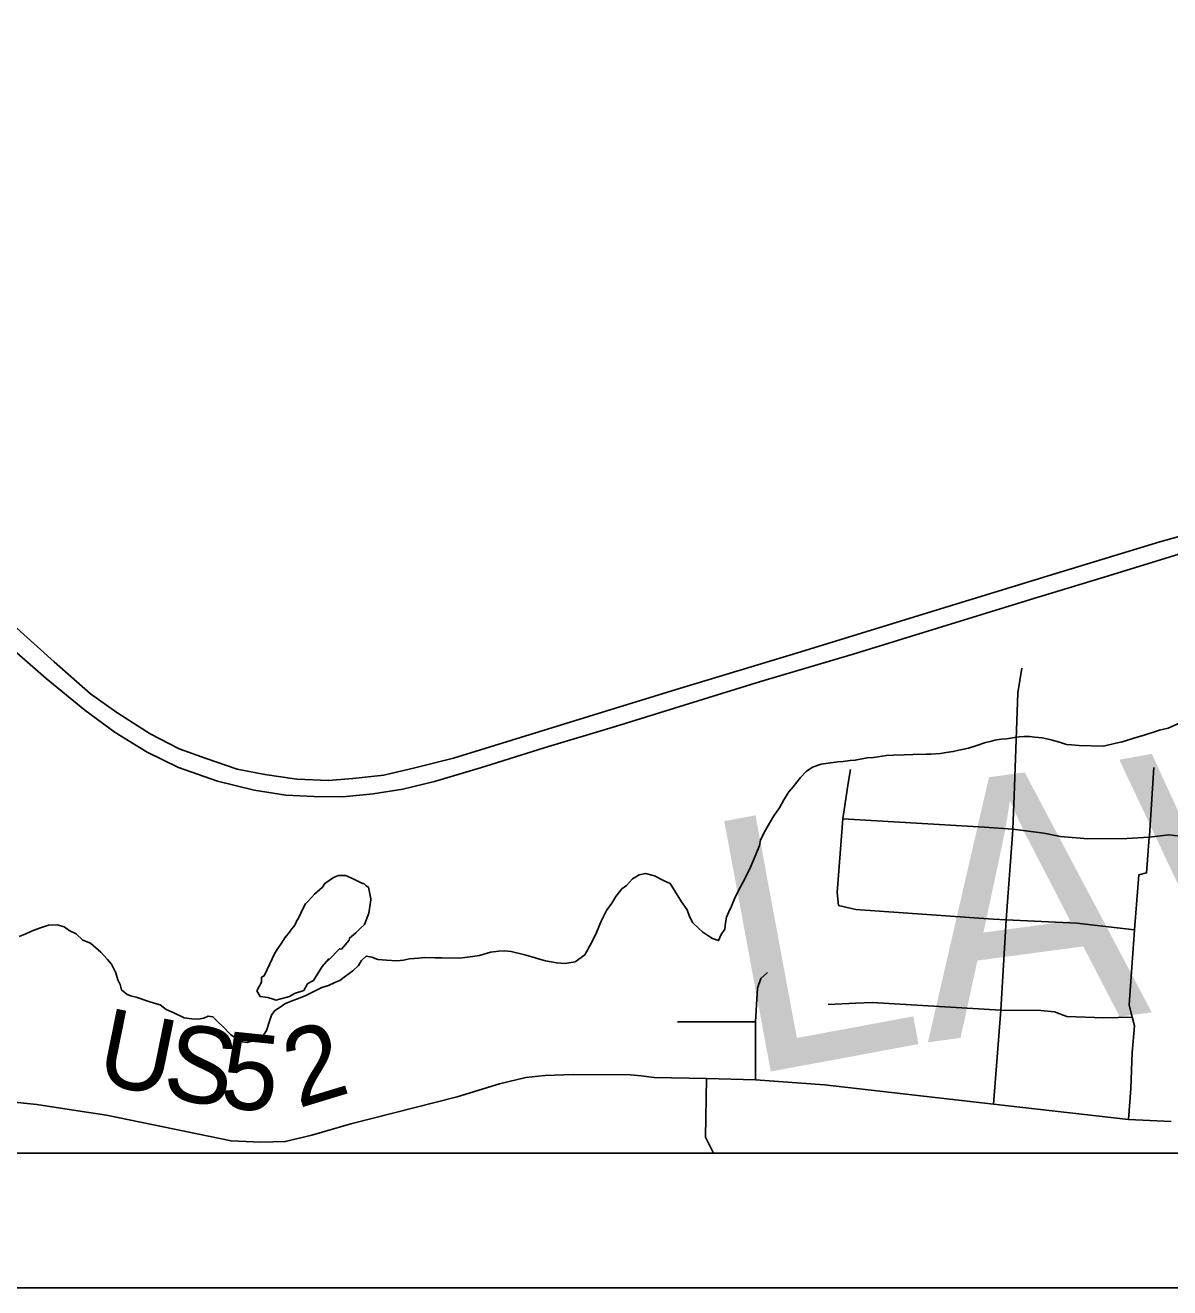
# Model space of a CAD drawing. Extents: x 0 to 45.4, y -2.2 to 22.
# Drawn here: x 5.991 to 6.842, y 14 to 14.939 of the extents above; entities that cross this region are included whole.
import ezdxf

# ---------------------------------------------------------------- set-up
doc = ezdxf.new("R2010")
doc.units = 0
for name, color, linetype in [('GM_X_Corporation', 7, 'Continuous'), ('GM_X_County_Road', 7, 'Continuous'), ('GM_X_County_Road_Text', 7, 'Continuous'), ('GM_X_County_Text', 7, 'Continuous'), ('GM_X_Minor_Lake', 7, 'Continuous'), ('GM_X_Minor_River', 7, 'Continuous'), ('GM_X_Township_Road', 7, 'Continuous'), ('GM_X_US_Route', 7, 'Continuous'), ('SH_Data', 7, 'Continuous')]:
    doc.layers.add(name, color=color, linetype=linetype)

msp = doc.modelspace()

# ---------------------------------------------------------------- linework, layer by layer
at = {"layer": 'GM_X_Corporation'}
for points in [[(5.60214, 14.1), (7.04133, 14.1), (7.11457, 14.11359), (7.56084, 14.21938), (7.62443, 14.24441), (8.08317, 14.39725), (8.47114, 14.54063), (8.59074, 14.58235), (8.82276, 14.67719), (8.9, 14.71924), (8.9, 20.9), (2.1, 20.9)], [(5.60214, 14.1), (7.04133, 14.1), (7.11457, 14.11359), (7.56084, 14.21938), (7.62443, 14.24441), (8.08317, 14.39725), (8.47114, 14.54063), (8.59074, 14.58235), (8.82276, 14.67719), (8.9, 14.71924), (8.9, 20.9), (6.29416, 20.9), (6.28823, 20.82258), (6.27886, 20.7002), (6.25885, 20.2929), (6.25376, 20.20761), (6.23458, 20.00881), (6.2236, 19.85421), (6.18097, 19.25389), (6.17632, 19.18849), (6.10611, 18.16069), (5.64203, 18.19082)]]:
    msp.add_lwpolyline(points, dxfattribs=at)
at = {"layer": 'GM_X_County_Road'}
msp.add_lwpolyline([(5.96573, 14.13987), (5.9995, 14.13616), (6.02998, 14.13163), (6.0514, 14.12833), (6.14408, 14.10938), (6.16578, 14.10835), (6.18421, 14.10871), (6.20409, 14.1134), (6.23287, 14.12181), (6.31216, 14.14198), (6.34364, 14.15174), (6.36299, 14.15624), (6.37715, 14.15781), (6.39853, 14.15871), (6.44082, 14.15826), (6.44892, 14.15758), (6.45859, 14.15646), (6.49741, 14.15552), (6.53392, 14.15475), (6.58504, 14.1509), (6.71072, 14.13661), (6.81118, 14.12521), (6.84298, 14.12365)], dxfattribs=at)
at = {"layer": 'GM_X_Minor_Lake'}
for points in [[(6.23473, 14.30404), (6.22906, 14.3067), (6.22377, 14.30671), (6.21999, 14.30519), (6.21356, 14.30065), (6.21204, 14.298), (6.20599, 14.2927), (6.20145, 14.28778), (6.19918, 14.28551), (6.19728, 14.28172), (6.19425, 14.27527), (6.19236, 14.27224), (6.19236, 14.27186), (6.19123, 14.26959), (6.1882, 14.2658), (6.1882, 14.26542), (6.18404, 14.2605), (6.18441, 14.26088), (6.18101, 14.25557), (6.17911, 14.25292), (6.17646, 14.24875), (6.17078, 14.23662), (6.16851, 14.23208), (6.16662, 14.23094), (6.16662, 14.22715), (6.16321, 14.22071)], [(6.16321, 14.22071), (6.16548, 14.21653), (6.17115, 14.21577), (6.17531, 14.21463), (6.1772, 14.21387), (6.18741, 14.21651), (6.19119, 14.21878), (6.198, 14.22104), (6.20065, 14.22597), (6.2033, 14.22748), (6.20519, 14.22861), (6.21163, 14.23884), (6.21655, 14.24453), (6.21655, 14.24377), (6.22449, 14.2521), (6.226, 14.25172), (6.23168, 14.25854), (6.23206, 14.26005), (6.2366, 14.26384), (6.23963, 14.26687), (6.24303, 14.27027), (6.24644, 14.27861), (6.24796, 14.28847), (6.24796, 14.28923), (6.24608, 14.29795), (6.24456, 14.29871), (6.24267, 14.30061), (6.24154, 14.30062), (6.23473, 14.30404)]]:
    msp.add_lwpolyline(points, dxfattribs=at)
at = {"layer": 'GM_X_Minor_River'}
for points in [[(6.79268, 14.40287), (6.80181, 14.40499), (6.80675, 14.40605), (6.81589, 14.40893), (6.82198, 14.41072), (6.83417, 14.41469), (6.84064, 14.4161), (6.85019, 14.42049)], [(6.3005, 14.24533), (6.31376, 14.2451), (6.32173, 14.2461), (6.32857, 14.24713), (6.33695, 14.24964), (6.34302, 14.2503), (6.34719, 14.25061), (6.35211, 14.25014), (6.36229, 14.24769), (6.36756, 14.24608), (6.37322, 14.24447), (6.37774, 14.24325), (6.38605, 14.24159), (6.3921, 14.24111), (6.3997, 14.2425), (6.40699, 14.24769), (6.41208, 14.2571), (6.41561, 14.26425), (6.41917, 14.27255), (6.4231, 14.28045), (6.42698, 14.28608), (6.4301, 14.29096), (6.43437, 14.29659), (6.43782, 14.29919), (6.44245, 14.30404), (6.44743, 14.307), (6.45199, 14.30806), (6.45878, 14.30642), (6.46591, 14.30251), (6.47042, 14.30053), (6.47374, 14.29554), (6.4789, 14.2871), (6.48296, 14.28095), (6.48476, 14.27598), (6.48733, 14.27138), (6.49143, 14.26752), (6.49479, 14.26442), (6.49853, 14.26208), (6.5019, 14.25974), (6.50642, 14.25815), (6.50839, 14.26267), (6.51112, 14.2668), (6.51158, 14.27135), (6.51241, 14.27551), (6.51399, 14.27966), (6.51596, 14.2838), (6.51873, 14.29059), (6.52265, 14.29812), (6.52617, 14.30452), (6.53011, 14.3128), (6.53406, 14.32223), (6.53683, 14.32902), (6.53766, 14.3328), (6.54041, 14.33845), (6.54432, 14.3456), (6.54745, 14.35086), (6.55172, 14.35686), (6.55485, 14.36288), (6.55875, 14.36889), (6.56184, 14.37264), (6.56727, 14.37938), (6.57151, 14.38386), (6.57612, 14.3872), (6.58259, 14.38937), (6.58791, 14.39004), (6.59512, 14.39105), (6.59892, 14.39137), (6.60423, 14.39204), (6.60802, 14.39235), (6.61677, 14.3941), (6.6217, 14.3944), (6.63119, 14.39576), (6.6365, 14.39605), (6.64446, 14.39629), (6.6509, 14.39656), (6.66075, 14.39677), (6.66416, 14.39671), (6.67137, 14.39735), (6.67555, 14.39804), (6.68087, 14.3987), (6.68505, 14.39977), (6.68885, 14.40047), (6.69227, 14.40117), (6.69761, 14.40298), (6.70485, 14.40551), (6.70827, 14.40621), (6.7117, 14.40729), (6.71663, 14.40797), (6.72043, 14.40828), (6.72498, 14.40896), (6.72992, 14.40964), (6.73371, 14.40995), (6.7375, 14.40989), (6.74166, 14.40944), (6.74695, 14.40897), (6.75262, 14.40773), (6.75978, 14.40571), (6.76505, 14.4041), (6.76883, 14.40366), (6.7745, 14.40318), (6.79268, 14.40287)], [(5.98637, 14.26128), (5.99133, 14.26309), (5.99553, 14.2653), (6.00163, 14.26748), (6.00811, 14.26965), (6.01456, 14.26992), (6.01983, 14.26831), (6.02357, 14.26559), (6.02883, 14.26322), (6.03367, 14.25858), (6.03931, 14.25621), (6.04715, 14.24962), (6.05198, 14.24422), (6.05495, 14.24076), (6.05825, 14.23424), (6.05967, 14.2289), (6.0615, 14.22545), (6.06257, 14.22164), (6.06668, 14.21815), (6.07007, 14.21696), (6.07346, 14.21614), (6.08288, 14.21294), (6.08664, 14.21174), (6.09117, 14.21052), (6.09565, 14.20703), (6.10091, 14.20466), (6.10918, 14.20073), (6.11484, 14.19987), (6.11939, 14.1998), (6.12357, 14.20048), (6.127, 14.20194), (6.1304, 14.20151), (6.13413, 14.19765), (6.13785, 14.19417), (6.14343, 14.18837), (6.14755, 14.18565), (6.15243, 14.18291), (6.15583, 14.18247), (6.1623, 14.18426), (6.16609, 14.18457), (6.17038, 14.19134), (6.17239, 14.19814), (6.17399, 14.20267), (6.17632, 14.20604), (6.18053, 14.20863), (6.18399, 14.21123), (6.18857, 14.21305), (6.19543, 14.21559), (6.19963, 14.21742), (6.20803, 14.22145), (6.21148, 14.22329), (6.21643, 14.22473), (6.22101, 14.22693), (6.22482, 14.22838), (6.22905, 14.23173), (6.23442, 14.23581), (6.23866, 14.23954), (6.24099, 14.2433), (6.24446, 14.24666), (6.24862, 14.24583), (6.25313, 14.24423), (6.25957, 14.24374), (6.26713, 14.24323), (6.27206, 14.24353), (6.27663, 14.24459), (6.28346, 14.24523), (6.28763, 14.24554), (6.29558, 14.24541), (6.3005, 14.24533)]]:
    msp.add_lwpolyline(points, dxfattribs=at)
at = {"layer": 'GM_X_Township_Road'}
for p, q in [((6.60282, 14.3752), (6.60438, 14.38537)), ((6.82669, 14.33613), (6.82991, 14.38699)), ((6.588, 14.21076), (6.60836, 14.21161)), ((6.47583, 14.19781), (6.53389, 14.19781))]:
    msp.add_line(p, q, dxfattribs=at)
for points in [[(6.72613, 14.36572), (6.72884, 14.44254), (6.73188, 14.46076)], [(6.59553, 14.28436), (6.59448, 14.29383), (6.59878, 14.34877), (6.60282, 14.3752)], [(6.72498, 14.3372), (6.72526, 14.34106), (6.72613, 14.36572)], [(6.59878, 14.34877), (6.70406, 14.34246), (6.72526, 14.34106), (6.74813, 14.3381), (6.76051, 14.33549), (6.78102, 14.33387), (6.81001, 14.3342), (6.82663, 14.33511), (6.84129, 14.3368), (6.85369, 14.33536), (6.88858, 14.3316)], [(6.71072, 14.13661), (6.71615, 14.20641), (6.72027, 14.2735), (6.72498, 14.3372)], [(6.82509, 14.31492), (6.82663, 14.33511), (6.82669, 14.33613)], [(6.81118, 14.12521), (6.81281, 14.14829), (6.8139, 14.17491), (6.81552, 14.19474), (6.8139, 14.20125), (6.81157, 14.21043), (6.81573, 14.2661), (6.81878, 14.30702), (6.8246, 14.30854), (6.82509, 14.31492)], [(6.59553, 14.28436), (6.6085, 14.28121), (6.71063, 14.27417)], [(6.71063, 14.27417), (6.72027, 14.2735), (6.77283, 14.27105), (6.81573, 14.2661)], [(6.53442, 14.20614), (6.53546, 14.2228), (6.53777, 14.2301), (6.54277, 14.23433)], [(6.53392, 14.15475), (6.53389, 14.19781), (6.53442, 14.20614)], [(6.60836, 14.21161), (6.62058, 14.21212), (6.71615, 14.20641), (6.74602, 14.20614), (6.75606, 14.20532), (6.76529, 14.20179), (6.79272, 14.20071), (6.8139, 14.20125)], [(6.49741, 14.15552), (6.49665, 14.11188), (6.50271, 14.10011), (6.50362, 14.1)]]:
    msp.add_lwpolyline(points, dxfattribs=at)
at = {"layer": 'GM_X_US_Route'}
for points in [[(5.97962, 14.49491), (6.01236, 14.46547), (6.0395, 14.44178), (6.05891, 14.4278), (6.08391, 14.41184), (6.10546, 14.40082), (6.12536, 14.39358), (6.14839, 14.38569), (6.16912, 14.38174), (6.19283, 14.37835), (6.21633, 14.3773), (6.23459, 14.37878), (6.25746, 14.38124), (6.28048, 14.38667), (6.30927, 14.39375), (6.3527, 14.40724), (6.40978, 14.42484), (6.47476, 14.44491), (6.56753, 14.47303), (6.66179, 14.50199), (6.7572, 14.5311), (6.83451, 14.55462), (6.90129, 14.57338)], [(6.32758, 14.38608), (6.33345, 14.38782), (6.37672, 14.40148), (6.43051, 14.4176), (6.48084, 14.43323), (6.53694, 14.4505), (6.60635, 14.47122), (6.66919, 14.49047), (6.73828, 14.51186), (6.79059, 14.52781), (6.85112, 14.54624)], [(5.90892, 14.53874), (5.93702, 14.51399), (5.97288, 14.48257), (6.00643, 14.45313), (6.03522, 14.42944), (6.05776, 14.41283), (6.08144, 14.39819), (6.10497, 14.38684), (6.13375, 14.37664), (6.16106, 14.37006), (6.18458, 14.36644), (6.20564, 14.36529), (6.22702, 14.36512), (6.24956, 14.36726), (6.2716, 14.37072), (6.29529, 14.37647), (6.32758, 14.38608)]]:
    msp.add_lwpolyline(points, dxfattribs=at)
at = {"layer": 'SH_Data'}
for p, q in [((2.1, 14.1), (8.9, 14.1)), ((2, 14), (9, 14))]:
    msp.add_line(p, q, dxfattribs=at)

# ---------------------------------------------------------------- texts
at = {"layer": 'GM_X_County_Road_Text'}
for s, rotation, p in [('U', 348.51968, (6.04196, 14.15289)), ('2', 16.91988, (6.19378, 14.13329)), ('S', 348.72096, (6.09117, 14.14289)), ('5', 354.10774, (6.13453, 14.13453))]:
    msp.add_text(s, height=0.05682, rotation=rotation, dxfattribs=at).set_placement(p)
at = {"layer": 'GM_X_County_Text'}
for s, rotation, p in [('W', 10.07584, (6.83638, 14.20604)), ('A', 7.60925, (6.66156, 14.18249)), ('L', 10.51619, (6.52478, 14.15703))]:
    msp.add_text(s, height=0.18939, rotation=rotation, dxfattribs=at).set_placement(p)

doc.saveas('drawing.dxf')
